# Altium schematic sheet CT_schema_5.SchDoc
size 143 x 123 mm
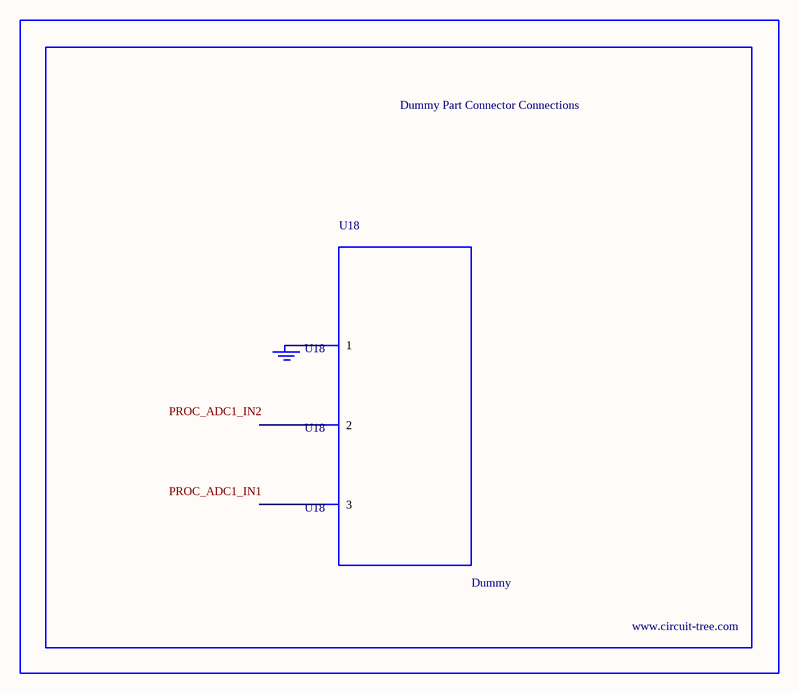
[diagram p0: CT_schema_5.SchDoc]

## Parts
BORDER4  (no value)
GND_INSTANCE_4_0  (no value)
U18  Dummy  [DUMMY_PACKAGE_174]

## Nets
NetGND_INSTANCE_4_0_0: GND_INSTANCE_4_0.0(GND) U18.1

Not connected (* = marked no-connect by the designer): U18 2 3

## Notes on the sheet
- Labels drawn without touching a wire or pin: PROC_ADC1_IN1, PROC_ADC1_IN2

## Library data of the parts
BORDER4 = BORDER_PAGE4
GND_INSTANCE_4_0 = GND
